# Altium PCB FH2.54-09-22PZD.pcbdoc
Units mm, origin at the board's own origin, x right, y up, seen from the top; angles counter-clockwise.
Board outline 68.82 x 15.21 mm, 2 copper layers (Top Layer, Bottom Layer), stack 0 mm thick; 1 components, 0 nets, 22 pads, 0 vias.
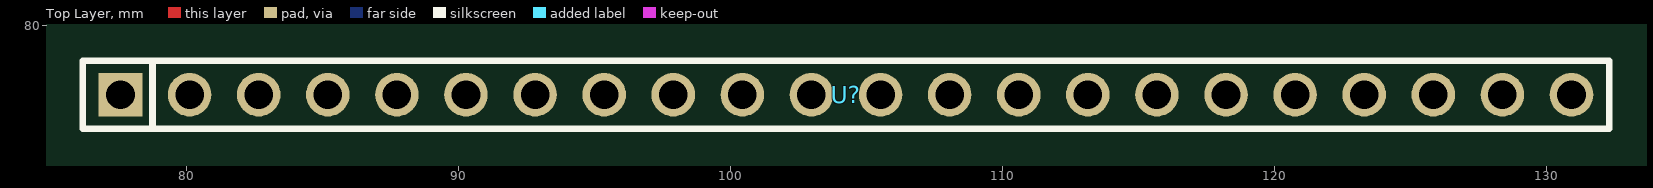
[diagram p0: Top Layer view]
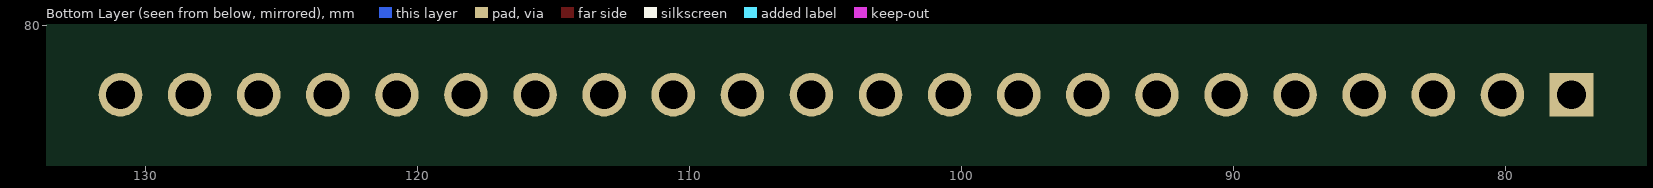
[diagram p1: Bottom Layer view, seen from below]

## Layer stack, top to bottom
Top Layer: signal copper (thickness not stored)
Bottom Layer: signal copper (thickness not stored)

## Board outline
138.669,69.85 69.85,69.85 69.85,85.06 138.669,85.06

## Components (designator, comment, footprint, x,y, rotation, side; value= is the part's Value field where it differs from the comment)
U? "FH2.54-09-22PZD" HDR-TH_22P-P2.54-V-F 104.259,77.46 r0 top

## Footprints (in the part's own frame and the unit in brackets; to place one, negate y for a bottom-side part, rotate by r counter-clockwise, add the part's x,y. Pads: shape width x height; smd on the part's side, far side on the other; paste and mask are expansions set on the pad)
HDR-TH_22P-P2.54-V-F [mil]
  rect 63x63 hole 41.3: 1(-1050,0)
  round 63 hole 41.3: 2(-950,0) 3(-850,0) 4(-750,0) 5(-650,0) 6(-550,0) 7(-450,0) 8(-350,0) 9(-250,0) 10(-150,0) 11(-50,0) 12(50,0) 13(150,0) 14(250,0) 15(350,0) 16(450,0) 17(550,0) 18(650,0) 19(750,0) 20(850,0) 21(950,0) 22(1050,0)
  silkscreen extent -1105,-49 1105,49

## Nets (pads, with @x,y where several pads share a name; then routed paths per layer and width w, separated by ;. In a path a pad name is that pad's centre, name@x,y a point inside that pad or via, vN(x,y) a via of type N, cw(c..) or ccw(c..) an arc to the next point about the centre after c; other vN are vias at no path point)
pads on no net: U?.1 U?.2 U?.3 U?.4 U?.5 U?.6 U?.7 U?.8 U?.9 U?.10 U?.11 U?.12 U?.13 U?.14 U?.15 U?.16 U?.17 U?.18 U?.19 U?.20 U?.21 U?.22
